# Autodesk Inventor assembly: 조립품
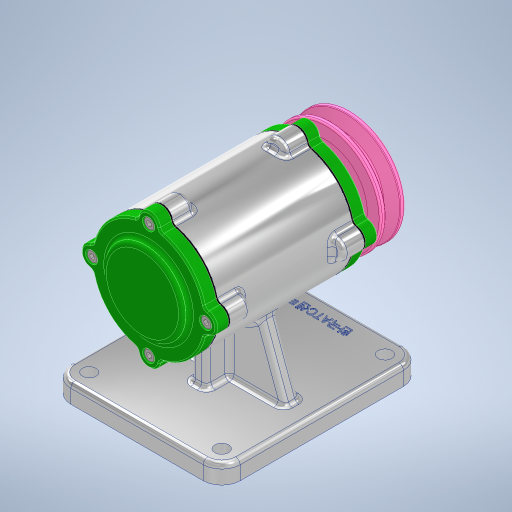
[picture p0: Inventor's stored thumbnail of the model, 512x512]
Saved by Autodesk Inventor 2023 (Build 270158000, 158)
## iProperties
Created: 2023-08
Part Number: 조립품
Document SubType Name: Assembly
Designer: asung
Author: asung
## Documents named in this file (12)
- C:\Users\asung\Desktop\730808V1004\조립품.iam
- C:\Users\asung\Desktop\730808V1004\본체.ipt
- C:\Users\asung\Desktop\730808V1004\730808V1004\베어링 6204.ipt
- C:\Users\asung\Desktop\730808V1004\730808V1004\개스킷.ipt
- C:\Users\asung\Desktop\730808V1004\730808V1004\앞커버.ipt
- C:\Users\asung\Desktop\730808V1004\730808V1004\뒤커버.ipt
- C:\Users\asung\Desktop\730808V1004\730808V1004\볼트 M4 x 12.ipt
- C:\Users\asung\Desktop\730808V1004\730808V1004\축.ipt
- C:\Users\asung\Desktop\730808V1004\730808V1004\오일 실.ipt
- C:\Users\asung\Desktop\730808V1004\730808V1004\키 4 x 4.ipt
- C:\Users\asung\Desktop\730808V1004\730808V1004\V-벨트풀리.ipt
- C:\Users\asung\Desktop\730808V1004\730808V1004\너트 M12 x 1.25.ipt
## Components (8 placed, 6 different names)
1. KS B 2023 6204 - 20 x 47 x 14:1
2. KS B 2023 6204 - 20 x 47 x 14:2
3. 개스킷:1
4. 개스킷:2
5. KS B 2804 D D - 20 32 8:1
6. KS B 1311 (I) 4 x 4 x 12:1
7. V-벨트풀리:1
8. KS B 1012 클래스 1 일반 - 미터 M12x1.25:1
